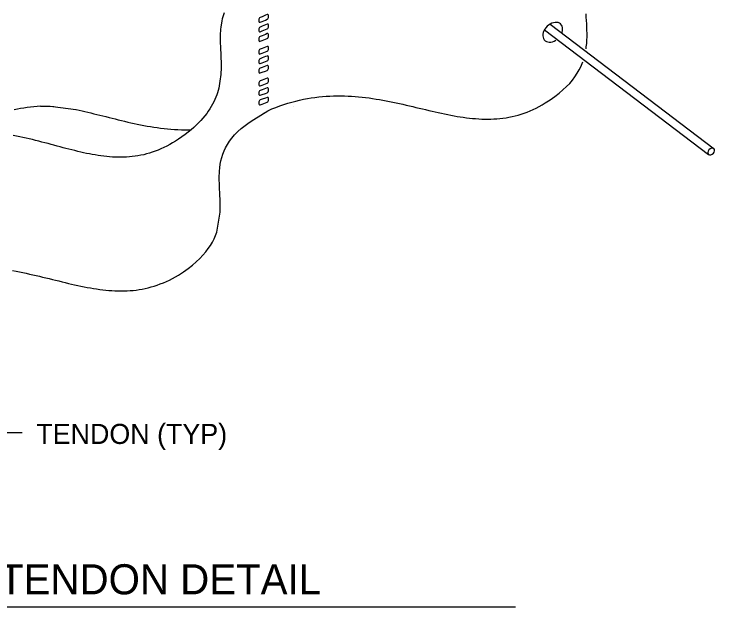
# Model space of a CAD drawing. Extents: x 638850 to 644908, y 297188 to 298900.
# Drawn here: x 639297 to 639401.8, y 297879 to 297967.6 of the extents above; entities that cross this region are included whole.
import ezdxf

# ---------------------------------------------------------------- set-up
doc = ezdxf.new("R2010")
doc.units = 0
for name, color, linetype in [('1', 7, 'Continuous'), ('16', 7, 'Continuous'), ('2', 7, 'Continuous'), ('4', 7, 'Continuous'), ('7', 7, 'Continuous')]:
    doc.layers.add(name, color=color, linetype=linetype)

msp = doc.modelspace()

# ---------------------------------------------------------------- linework, layer by layer
at = {"layer": '1'}
for p, q in [((639377.1, 297966.1), (639401.62, 297947.45)), ((639376.27, 297965.25), (639400.8, 297946.59))]:
    msp.add_line(p, q, dxfattribs=at)
msp.add_arc((639303.18, 297925.02), 28.92, 94.4334, 102.4037, dxfattribs=at)
for centre, major_axis, start_param in [((639377.51, 297964.89), (-1.2, -1.2), 2.18443), ((639401.19, 297947.05), (-0.416, -0.414), 1.264481)]:
    msp.add_ellipse(centre, major_axis=major_axis, ratio=0.717222, start_param=start_param, end_param=7.533439, dxfattribs=at)
at = {"layer": '16'}
for points in [[(639334.81, 297966.83), (639334.9, 297966.89), (639334.98, 297966.98), (639335.01, 297967.09), (639335.01, 297967.09), (639335.01, 297967.18), (639335.01, 297967.34), (639335.01, 297967.43), (639335.01, 297967.43), (639334.98, 297967.51), (639334.9, 297967.55), (639334.81, 297967.54), (639334.81, 297967.54), (639334.55, 297967.43), (639334.04, 297967.21), (639333.77, 297967.11), (639333.77, 297967.11), (639333.68, 297967.03), (639333.6, 297966.94), (639333.57, 297966.83), (639333.57, 297966.83), (639333.57, 297966.75), (639333.57, 297966.58), (639333.57, 297966.5), (639333.57, 297966.5), (639333.6, 297966.41), (639333.68, 297966.38), (639333.77, 297966.38), (639333.77, 297966.38), (639334.04, 297966.5), (639334.55, 297966.71), (639334.81, 297966.83), (639334.81, 297966.83), (639334.81, 297966.83)], [(639334.81, 297965.39), (639334.9, 297965.45), (639334.98, 297965.55), (639335.01, 297965.66), (639335.01, 297965.66), (639335.01, 297965.75), (639335.01, 297965.9), (639335.01, 297965.99), (639335.01, 297965.99), (639334.98, 297966.09), (639334.9, 297966.12), (639334.81, 297966.1), (639334.81, 297966.1), (639334.55, 297965.99), (639334.04, 297965.79), (639333.77, 297965.67), (639333.77, 297965.67), (639333.68, 297965.61), (639333.6, 297965.52), (639333.57, 297965.41), (639333.57, 297965.41), (639333.57, 297965.33), (639333.57, 297965.16), (639333.57, 297965.08), (639333.57, 297965.08), (639333.6, 297964.99), (639333.68, 297964.95), (639333.77, 297964.96), (639333.77, 297964.96), (639334.04, 297965.08), (639334.55, 297965.28), (639334.81, 297965.39), (639334.81, 297965.39), (639334.81, 297965.39)], [(639334.81, 297963.95), (639334.9, 297964.03), (639334.98, 297964.12), (639335.01, 297964.23), (639335.01, 297964.23), (639335.01, 297964.31), (639335.01, 297964.48), (639335.01, 297964.56), (639335.01, 297964.56), (639334.98, 297964.65), (639334.9, 297964.68), (639334.81, 297964.68), (639334.81, 297964.68), (639334.55, 297964.57), (639334.04, 297964.36), (639333.77, 297964.25), (639333.77, 297964.25), (639333.68, 297964.19), (639333.6, 297964.1), (639333.57, 297963.99), (639333.57, 297963.99), (639333.57, 297963.9), (639333.57, 297963.74), (639333.57, 297963.66), (639333.57, 297963.66), (639333.6, 297963.57), (639333.68, 297963.52), (639333.77, 297963.54), (639333.77, 297963.54), (639334.04, 297963.65), (639334.55, 297963.85), (639334.81, 297963.95), (639334.81, 297963.95), (639334.81, 297963.95)], [(639334.81, 297962.06), (639334.9, 297962.12), (639334.98, 297962.21), (639335.01, 297962.32), (639335.01, 297962.32), (639335.01, 297962.4), (639335.01, 297962.57), (639335.01, 297962.64), (639335.01, 297962.64), (639334.98, 297962.74), (639334.9, 297962.78), (639334.81, 297962.77), (639334.81, 297962.77), (639334.55, 297962.66), (639334.04, 297962.46), (639333.77, 297962.35), (639333.77, 297962.35), (639333.68, 297962.29), (639333.6, 297962.19), (639333.57, 297962.09), (639333.57, 297962.09), (639333.57, 297962.01), (639333.57, 297961.84), (639333.57, 297961.76), (639333.57, 297961.76), (639333.6, 297961.67), (639333.68, 297961.62), (639333.77, 297961.64), (639333.77, 297961.64), (639334.04, 297961.75), (639334.55, 297961.95), (639334.81, 297962.06), (639334.81, 297962.06), (639334.81, 297962.06)], [(639334.81, 297960.62), (639334.9, 297960.68), (639334.98, 297960.77), (639335.01, 297960.88), (639335.01, 297960.88), (639335.01, 297960.97), (639335.01, 297961.13), (639335.01, 297961.22), (639335.01, 297961.22), (639334.98, 297961.3), (639334.9, 297961.35), (639334.81, 297961.33), (639334.81, 297961.33), (639334.55, 297961.24), (639334.04, 297961.04), (639333.77, 297960.93), (639333.77, 297960.93), (639333.68, 297960.87), (639333.6, 297960.77), (639333.57, 297960.67), (639333.57, 297960.67), (639333.57, 297960.59), (639333.57, 297960.42), (639333.57, 297960.34), (639333.57, 297960.34), (639333.6, 297960.25), (639333.68, 297960.2), (639333.77, 297960.22), (639333.77, 297960.22), (639334.04, 297960.33), (639334.55, 297960.51), (639334.81, 297960.62), (639334.81, 297960.62), (639334.81, 297960.62)], [(639334.81, 297959.18), (639334.9, 297959.25), (639334.98, 297959.35), (639335.01, 297959.45), (639335.01, 297959.45), (639335.01, 297959.54), (639335.01, 297959.69), (639335.01, 297959.79), (639335.01, 297959.79), (639334.98, 297959.88), (639334.9, 297959.91), (639334.81, 297959.91), (639334.81, 297959.91), (639334.55, 297959.8), (639334.04, 297959.62), (639333.77, 297959.51), (639333.77, 297959.51), (639333.68, 297959.45), (639333.6, 297959.35), (639333.57, 297959.25), (639333.57, 297959.25), (639333.57, 297959.15), (639333.57, 297959), (639333.57, 297958.92), (639333.57, 297958.92), (639333.6, 297958.83), (639333.68, 297958.78), (639333.77, 297958.8), (639333.77, 297958.8), (639334.04, 297958.91), (639334.55, 297959.09), (639334.81, 297959.18), (639334.81, 297959.18), (639334.81, 297959.18)], [(639334.81, 297957.28), (639334.92, 297957.35), (639334.98, 297957.44), (639335.01, 297957.55), (639335.01, 297957.55), (639335.01, 297957.64), (639335.01, 297957.79), (639335.01, 297957.89), (639335.01, 297957.89), (639334.98, 297957.96), (639334.92, 297958.01), (639334.81, 297958), (639334.81, 297958), (639334.55, 297957.9), (639334.04, 297957.72), (639333.77, 297957.61), (639333.77, 297957.61), (639333.68, 297957.55), (639333.6, 297957.45), (639333.59, 297957.35), (639333.59, 297957.35), (639333.59, 297957.27), (639333.59, 297957.1), (639333.59, 297957.02), (639333.59, 297957.02), (639333.6, 297956.93), (639333.68, 297956.9), (639333.77, 297956.9), (639333.77, 297956.9), (639334.04, 297957), (639334.55, 297957.19), (639334.81, 297957.28), (639334.81, 297957.28), (639334.81, 297957.28)], [(639334.81, 297955.85), (639334.92, 297955.91), (639334.98, 297956), (639335.01, 297956.11), (639335.01, 297956.11), (639335.01, 297956.2), (639335.01, 297956.36), (639335.01, 297956.45), (639335.01, 297956.45), (639334.98, 297956.53), (639334.92, 297956.57), (639334.81, 297956.57), (639334.81, 297956.57), (639334.55, 297956.46), (639334.04, 297956.28), (639333.77, 297956.19), (639333.77, 297956.19), (639333.68, 297956.12), (639333.6, 297956.03), (639333.59, 297955.92), (639333.59, 297955.92), (639333.59, 297955.85), (639333.59, 297955.68), (639333.59, 297955.6), (639333.59, 297955.6), (639333.6, 297955.51), (639333.68, 297955.46), (639333.77, 297955.48), (639333.77, 297955.48), (639334.04, 297955.57), (639334.55, 297955.75), (639334.81, 297955.85), (639334.81, 297955.85), (639334.81, 297955.85)], [(639334.81, 297954.43), (639334.92, 297954.49), (639334.98, 297954.58), (639335.01, 297954.67), (639335.01, 297954.67), (639335.01, 297954.77), (639335.01, 297954.94), (639335.01, 297955.01), (639335.01, 297955.01), (639334.98, 297955.11), (639334.92, 297955.15), (639334.81, 297955.14), (639334.81, 297955.14), (639334.55, 297955.04), (639334.04, 297954.86), (639333.77, 297954.77), (639333.77, 297954.77), (639333.68, 297954.7), (639333.6, 297954.61), (639333.59, 297954.5), (639333.59, 297954.5), (639333.59, 297954.43), (639333.59, 297954.26), (639333.59, 297954.18), (639333.59, 297954.18), (639333.6, 297954.09), (639333.68, 297954.04), (639333.77, 297954.06), (639333.77, 297954.06), (639334.04, 297954.15), (639334.55, 297954.33), (639334.81, 297954.43), (639334.81, 297954.43), (639334.81, 297954.43)]]:
    msp.add_lwpolyline(points, dxfattribs=at)
at = {"layer": '2'}
for p, q in [((639339.66, 297954.74), (639340.25, 297954.86)), ((639340.25, 297954.86), (639340.82, 297954.97)), ((639340.82, 297954.97), (639341.39, 297955.06)), ((639341.39, 297955.06), (639341.94, 297955.15)), ((639341.94, 297955.15), (639342.52, 297955.21)), ((639342.52, 297955.21), (639343.07, 297955.28)), ((639343.07, 297955.28), (639343.63, 297955.32)), ((639343.63, 297955.32), (639344.18, 297955.35)), ((639344.18, 297955.35), (639344.74, 297955.37)), ((639344.74, 297955.37), (639345.28, 297955.39)), ((639345.28, 297955.39), (639345.82, 297955.39)), ((639345.82, 297955.39), (639346.36, 297955.37)), ((639346.36, 297955.37), (639346.9, 297955.35)), ((639346.9, 297955.35), (639347.42, 297955.32)), ((639347.42, 297955.32), (639347.97, 297955.29)), ((639347.97, 297955.29), (639348.49, 297955.25)), ((639348.49, 297955.25), (639349.02, 297955.19)), ((639302.79, 297953.79), (639306.19, 297953.33)), ((639336.11, 297953.66), (639336.71, 297953.87)), ((639336.71, 297953.87), (639337.31, 297954.09)), ((639337.31, 297954.09), (639337.91, 297954.27)), ((639337.91, 297954.27), (639338.5, 297954.44)), ((639338.5, 297954.44), (639339.09, 297954.6)), ((639338.74, 297953.84), (639338.74, 297953.84)), ((639339.09, 297954.6), (639339.66, 297954.74)), ((639332.83, 297951.85), (639334.9, 297953.16)), ((639334.28, 297952.89), (639334.28, 297952.89)), ((639334.9, 297953.16), (639335.5, 297953.42)), ((639335.5, 297953.42), (639336.11, 297953.66)), ((639332.13, 297951.4), (639332.83, 297951.85)), ((639330.93, 297950.49), (639331.5, 297950.95)), ((639331.5, 297950.95), (639332.13, 297951.4)), ((639329.54, 297949.07), (639329.95, 297949.55)), ((639329.95, 297949.55), (639330.42, 297950.03)), ((639330.42, 297950.03), (639330.93, 297950.49)), ((639328.87, 297948.13), (639329.18, 297948.59)), ((639329.18, 297948.59), (639329.54, 297949.07)), ((639328.36, 297947.14), (639328.59, 297947.63)), ((639328.59, 297947.63), (639328.87, 297948.13)), ((639328.02, 297946.15), (639328.18, 297946.65)), ((639328.18, 297946.65), (639328.36, 297947.14)), ((639327.81, 297945.15), (639327.9, 297945.66)), ((639327.9, 297945.66), (639328.02, 297946.15)), ((639327.68, 297944.14), (639327.73, 297944.64)), ((639327.73, 297944.64), (639327.81, 297945.15)), ((639327.65, 297943.12), (639327.68, 297944.14)), ((639327.65, 297942.72), (639327.65, 297943.12)), ((639327.65, 297943.12), (639327.65, 297943.12)), ((639327.67, 297942.31), (639327.65, 297942.72)), ((639327.68, 297941.9), (639327.67, 297942.31)), ((639327.71, 297941.41), (639327.68, 297941.9)), ((639327.74, 297940.93), (639327.71, 297941.41)), ((639327.76, 297940.44), (639327.74, 297940.93)), ((639327.79, 297939.96), (639327.76, 297940.44)), ((639327.81, 297939.47), (639327.79, 297939.96)), ((639327.81, 297938.97), (639327.81, 297939.47)), ((639327.79, 297937.98), (639327.81, 297938.48)), ((639327.81, 297938.48), (639327.81, 297938.97)), ((639327.27, 297934.99), (639327.79, 297937.98))]:
    msp.add_line(p, q, dxfattribs=at)
for points in [[(639328.39, 297967.77), (639328.28, 297967.48), (639328.19, 297967.19), (639328.1, 297966.88), (639328.04, 297966.58), (639327.98, 297966.27), (639327.93, 297965.98), (639327.88, 297965.67), (639327.85, 297965.36), (639327.82, 297965.05), (639327.81, 297964.75), (639327.81, 297964.42), (639327.79, 297964.11), (639327.79, 297963.8), (639327.81, 297963.48), (639327.81, 297963.17), (639327.82, 297962.85), (639327.84, 297962.52), (639327.85, 297962.2), (639327.87, 297961.87), (639327.87, 297961.55), (639327.88, 297961.23), (639327.9, 297960.9), (639327.92, 297960.56), (639327.92, 297960.24), (639327.92, 297959.91), (639327.92, 297959.57), (639327.92, 297959.25), (639327.9, 297958.91), (639327.87, 297958.57), (639327.85, 297958.23), (639327.81, 297957.9), (639327.76, 297957.56), (639327.71, 297957.22), (639327.65, 297956.89), (639327.58, 297956.55), (639327.48, 297956.19), (639327.37, 297955.85), (639327.27, 297955.51), (639327.14, 297955.17), (639326.99, 297954.83), (639326.83, 297954.48), (639326.65, 297954.14), (639326.46, 297953.78), (639326.25, 297953.44), (639326.01, 297953.08), (639325.77, 297952.75), (639325.5, 297952.39), (639325.21, 297952.05), (639324.9, 297951.7), (639324.56, 297951.35), (639324.21, 297951), (639323.84, 297950.65), (639323.44, 297950.29), (639323, 297949.95), (639322.54, 297949.6), (639322.06, 297949.24), (639321.55, 297948.9), (639321.55, 297948.9), (639321.55, 297948.9)], [(639382.49, 297962.39), (639382.53, 297962.72), (639382.59, 297963.22), (639382.62, 297963.71), (639382.64, 297964.2), (639382.64, 297964.7), (639382.62, 297965.19), (639382.61, 297965.67), (639382.58, 297966.16), (639382.56, 297966.66), (639382.53, 297967.14), (639382.5, 297967.62)], [(639349.02, 297955.19), (639349.53, 297955.12), (639350.05, 297955.06), (639350.56, 297954.98), (639351.09, 297954.9), (639351.6, 297954.83), (639352.11, 297954.74), (639352.6, 297954.65), (639353.11, 297954.54), (639353.61, 297954.44), (639354.11, 297954.33), (639354.61, 297954.23), (639355.1, 297954.12), (639355.6, 297954.01), (639356.08, 297953.89), (639356.57, 297953.78), (639357.05, 297953.66), (639357.54, 297953.55), (639358.02, 297953.42), (639358.5, 297953.32), (639358.98, 297953.21), (639359.46, 297953.08), (639359.92, 297952.97), (639360.4, 297952.87), (639360.88, 297952.78), (639361.34, 297952.67), (639361.81, 297952.58), (639362.28, 297952.48), (639362.75, 297952.4), (639363.21, 297952.31), (639363.67, 297952.25), (639364.14, 297952.17), (639364.6, 297952.11), (639365.06, 297952.05), (639365.51, 297952), (639365.97, 297951.97), (639366.44, 297951.94), (639366.89, 297951.91), (639367.35, 297951.91), (639367.8, 297951.89), (639368.26, 297951.91), (639368.71, 297951.93), (639369.16, 297951.96), (639369.62, 297952), (639370.07, 297952.05), (639370.52, 297952.11), (639370.96, 297952.19), (639371.43, 297952.28), (639371.87, 297952.39), (639372.32, 297952.51), (639372.77, 297952.65), (639373.22, 297952.79), (639373.68, 297952.96), (639374.11, 297953.14), (639374.56, 297953.35), (639375.01, 297953.56), (639375.47, 297953.79), (639375.92, 297954.04), (639376.37, 297954.32), (639376.37, 297954.32), (639377.12, 297954.8), (639377.82, 297955.29), (639378.47, 297955.79), (639379.04, 297956.27), (639379.57, 297956.76), (639380.05, 297957.25), (639380.46, 297957.75), (639380.83, 297958.24), (639381.17, 297958.75), (639381.47, 297959.25), (639381.71, 297959.74), (639381.93, 297960.23), (639382.01, 297960.47)], [(639300.94, 297953.85), (639301.07, 297953.86), (639301.5, 297953.86), (639301.94, 297953.84), (639302.35, 297953.83), (639302.79, 297953.79), (639302.94, 297953.78)], [(639306.19, 297953.33), (639306.26, 297953.32), (639306.69, 297953.22), (639307.14, 297953.13), (639307.57, 297953.02), (639308.02, 297952.93), (639308.47, 297952.82), (639308.92, 297952.71), (639309.37, 297952.61), (639309.81, 297952.5), (639310.26, 297952.37), (639310.71, 297952.27), (639311.17, 297952.14), (639311.64, 297952.03), (639312.1, 297951.93), (639312.56, 297951.8), (639313.03, 297951.69), (639313.49, 297951.57), (639313.97, 297951.46), (639314.45, 297951.36), (639314.93, 297951.25), (639315.4, 297951.15), (639315.88, 297951.05), (639316.38, 297950.95), (639316.87, 297950.86), (639317.37, 297950.78), (639317.86, 297950.71), (639318.37, 297950.63), (639318.88, 297950.57), (639319.39, 297950.51), (639319.9, 297950.44), (639320.42, 297950.4), (639320.95, 297950.37), (639321.47, 297950.34), (639322.02, 297950.32), (639322.54, 297950.31), (639323.08, 297950.31), (639323.45, 297950.31)], [(639321.55, 297948.9), (639321.1, 297948.61), (639320.67, 297948.36), (639320.24, 297948.1), (639319.79, 297947.87), (639319.36, 297947.65), (639318.93, 297947.45), (639318.5, 297947.28), (639318.06, 297947.11), (639317.63, 297946.95), (639317.2, 297946.82), (639316.78, 297946.69), (639316.35, 297946.58), (639315.91, 297946.49), (639315.5, 297946.41), (639315.06, 297946.35), (639314.65, 297946.29), (639314.22, 297946.26), (639313.8, 297946.23), (639313.37, 297946.21), (639312.95, 297946.2), (639312.52, 297946.2), (639312.08, 297946.21), (639311.67, 297946.23), (639311.23, 297946.26), (639310.82, 297946.31), (639310.39, 297946.35), (639309.95, 297946.4), (639309.54, 297946.46), (639309.1, 297946.54), (639308.67, 297946.62), (639308.24, 297946.69), (639307.81, 297946.78), (639307.37, 297946.88), (639306.94, 297946.97), (639306.51, 297947.08), (639306.06, 297947.19), (639305.63, 297947.29), (639305.18, 297947.4), (639304.73, 297947.51), (639304.3, 297947.63), (639303.85, 297947.76), (639303.4, 297947.88), (639302.94, 297947.99), (639302.5, 297948.11), (639302.05, 297948.24), (639301.58, 297948.36), (639301.12, 297948.47), (639300.66, 297948.59), (639300.19, 297948.7), (639299.71, 297948.83), (639299.25, 297948.93), (639298.77, 297949.04), (639298.29, 297949.15), (639297.81, 297949.26), (639297.32, 297949.35), (639296.84, 297949.44)], [(639317.94, 297926.92), (639318.39, 297927.08), (639318.83, 297927.25), (639319.3, 297927.42), (639319.75, 297927.62), (639320.19, 297927.84), (639320.64, 297928.07), (639321.1, 297928.31), (639321.55, 297928.59), (639321.55, 297928.59), (639322.31, 297929.09), (639323, 297929.57), (639323.64, 297930.06), (639324.22, 297930.55), (639324.75, 297931.05), (639325.21, 297931.54), (639325.65, 297932.04), (639326.01, 297932.53), (639326.35, 297933.02), (639326.63, 297933.52), (639326.89, 297934.01), (639327.1, 297934.51), (639327.27, 297934.99)], [(639296.76, 297929.26), (639297.27, 297929.16), (639297.77, 297929.07), (639298.28, 297928.96), (639298.77, 297928.85), (639299.28, 297928.74), (639299.78, 297928.64), (639300.27, 297928.51), (639300.75, 297928.41), (639301.24, 297928.28), (639301.74, 297928.16), (639302.22, 297928.05), (639302.71, 297927.93), (639303.19, 297927.81), (639303.67, 297927.7), (639304.14, 297927.57), (639304.63, 297927.46), (639305.09, 297927.34), (639305.57, 297927.23), (639306.03, 297927.12), (639306.51, 297927.03), (639306.97, 297926.92), (639307.44, 297926.83), (639307.91, 297926.74), (639308.38, 297926.66), (639308.84, 297926.58), (639309.3, 297926.51), (639309.77, 297926.44), (639310.22, 297926.38), (639310.68, 297926.34), (639311.14, 297926.29), (639311.59, 297926.26), (639312.05, 297926.23), (639312.5, 297926.22), (639312.96, 297926.22), (639313.41, 297926.22), (639313.88, 297926.23), (639314.32, 297926.26), (639314.77, 297926.29), (639315.24, 297926.34), (639315.68, 297926.4), (639316.13, 297926.48), (639316.58, 297926.57), (639317.04, 297926.68), (639317.49, 297926.8), (639317.94, 297926.92)]]:
    msp.add_lwpolyline(points, dxfattribs=at)
at = {"layer": '4'}
msp.add_line((639236.67, 297878.95), (639371.95, 297878.95), dxfattribs=at)
at = {"layer": '7'}
msp.add_line((639280.84, 297905.02), (639298.16, 297905.02), dxfattribs=at)

# ---------------------------------------------------------------- texts
at = {"layer": '1'}
msp.add_text('TENDON (TYP)', height=3, dxfattribs=at).set_placement((639300.3, 297903.33))
at = {"layer": '4'}
msp.add_text('RESTRAINT CLIP & TENDON DETAIL', height=4.5, dxfattribs=at).set_placement((639238.22, 297880.84))

doc.saveas('drawing.dxf')
